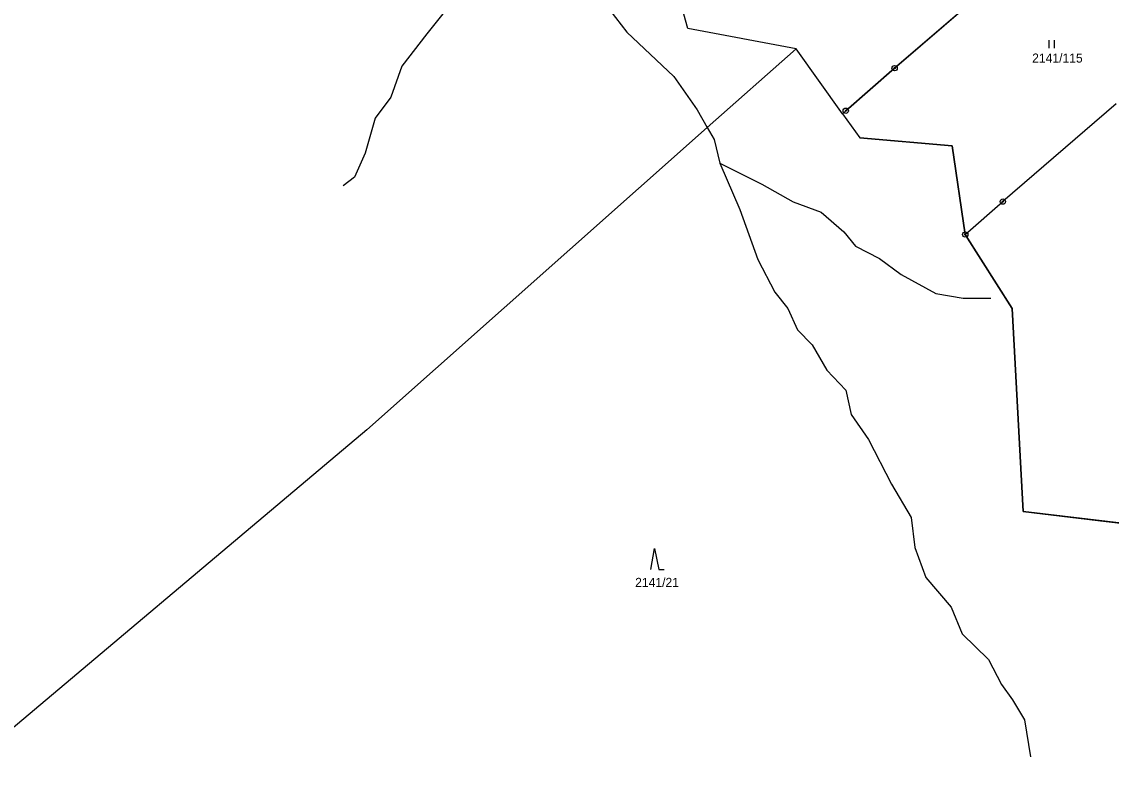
# Model space of a CAD drawing. Extents: x -439246 to -433691, y -1130252 to -1121148.
# Drawn here: x -435202 to -434997.5, y -1125793.1 to -1125650.6 of the extents above; entities that cross this region are included whole.
import ezdxf

# ---------------------------------------------------------------- set-up
doc = ezdxf.new("R2010")
doc.units = 0
for name, color, linetype in [('Vrstva 1', 7, 'Continuous'), ('Vrstva 16', 7, 'Continuous'), ('Vrstva 18', 7, 'Continuous'), ('Vrstva 24', 7, 'Continuous'), ('Vrstva 25', 7, 'Continuous'), ('Vrstva 4', 7, 'Continuous'), ('Vrstva 52', 7, 'Continuous')]:
    doc.layers.add(name, color=color, linetype=linetype)

msp = doc.modelspace()

# ---------------------------------------------------------------- linework, layer by layer
at = {"layer": 'Vrstva 1'}
for points in [[(-435038.13, -1125659.3), (-435014.64, -1125639.05)], [(-435076.96, -1125651.87), (-435078.02, -1125648.06)], [(-435056.6, -1125655.67), (-435076.96, -1125651.87)], [(-435056.6, -1125655.67), (-435073.31, -1125670.43)], [(-435047.94, -1125667.84), (-435056.6, -1125655.67)], [(-435047.31, -1125667.29), (-435038.13, -1125659.3)], [(-434996.55, -1125665.97), (-435017.82, -1125684.35)], [(-435047.31, -1125667.29), (-435047.94, -1125667.84)], [(-435047.94, -1125667.84), (-435044.69, -1125672.4)], [(-435073.31, -1125670.43), (-435137.19, -1125727.15)], [(-435027.36, -1125673.85), (-435044.69, -1125672.4)], [(-435024.88, -1125690.52), (-435027.36, -1125673.85)], [(-435024.88, -1125690.52), (-435017.82, -1125684.35)], [(-435016.08, -1125704.39), (-435024.88, -1125690.52)], [(-435013.98, -1125742.52), (-435016.08, -1125704.39)], [(-435137.19, -1125727.15), (-435215.58, -1125793.11)], [(-434962.79, -1125748.54), (-435013.98, -1125742.52)]]:
    msp.add_lwpolyline(points, dxfattribs=at)
at = {"layer": 'Vrstva 24'}
for centre, radius in [((-435038.13, -1125659.3), 0.5), ((-435038.13, -1125659.3), 0.1), ((-435047.31, -1125667.29), 0.5), ((-435047.31, -1125667.29), 0.1), ((-435017.82, -1125684.35), 0.5), ((-435017.82, -1125684.35), 0.1), ((-435024.88, -1125690.52), 0.5), ((-435024.88, -1125690.52), 0.1)]:
    msp.add_circle(centre, radius, dxfattribs=at)
at = {"layer": 'Vrstva 25'}
for p, q in [((-435009.1, -1125655.55), (-435009.1, -1125654.05)), ((-435008.1, -1125655.55), (-435008.1, -1125654.05))]:
    msp.add_line(p, q, dxfattribs=at)
msp.add_lwpolyline([(-435083.91, -1125753.41), (-435083.21, -1125749.41), (-435082.41, -1125753.41), (-435081.41, -1125753.41)], dxfattribs=at)
at = {"layer": 'Vrstva 4'}
for points in [[(-435121.18, -1125646.9), (-435125.92, -1125652.84)], [(-435091.59, -1125648.42), (-435088.4, -1125652.52)], [(-435088.4, -1125652.52), (-435079.57, -1125660.87)], [(-435125.92, -1125652.84), (-435130.62, -1125658.9)], [(-435130.62, -1125658.9), (-435132.71, -1125664.74)], [(-435079.57, -1125660.87), (-435075.17, -1125667.14)], [(-435132.71, -1125664.74), (-435135.63, -1125668.7)], [(-435135.63, -1125668.7), (-435137.5, -1125675.28)], [(-435075.17, -1125667.14), (-435073.31, -1125670.43)], [(-435073.31, -1125670.43), (-435072.03, -1125672.7)], [(-435072.03, -1125672.7), (-435070.92, -1125677.14)], [(-435137.5, -1125675.28), (-435139.55, -1125679.73)], [(-435070.92, -1125677.14), (-435067.21, -1125685.85)], [(-435070.92, -1125677.14), (-435063.09, -1125681.04)], [(-435139.55, -1125679.73), (-435141.68, -1125681.38)], [(-435063.09, -1125681.04), (-435057.21, -1125684.37)], [(-435057.21, -1125684.37), (-435051.91, -1125686.31)], [(-435067.21, -1125685.85), (-435063.79, -1125695.22)], [(-435051.91, -1125686.31), (-435047.67, -1125690.01)], [(-435047.67, -1125690.01), (-435045.45, -1125692.68)], [(-435045.45, -1125692.68), (-435040.97, -1125695.03)], [(-435063.79, -1125695.22), (-435060.63, -1125701.32)], [(-435040.97, -1125695.03), (-435036.9, -1125697.99)], [(-435036.9, -1125697.99), (-435030.38, -1125701.56)], [(-435060.63, -1125701.32), (-435058.17, -1125704.42)], [(-435030.38, -1125701.56), (-435025.29, -1125702.45)], [(-435025.29, -1125702.45), (-435020.05, -1125702.45)], [(-435058.17, -1125704.42), (-435056.35, -1125708.38)], [(-435056.35, -1125708.38), (-435053.63, -1125711.22)], [(-435053.63, -1125711.22), (-435050.85, -1125715.99)], [(-435050.85, -1125715.99), (-435047.28, -1125719.74)], [(-435047.28, -1125719.74), (-435046.28, -1125724.27)], [(-435046.28, -1125724.27), (-435043.03, -1125728.98)], [(-435043.03, -1125728.98), (-435038.7, -1125737.35)], [(-435038.7, -1125737.35), (-435035.04, -1125743.63)], [(-435035.04, -1125743.63), (-435034.34, -1125749.24)], [(-435034.34, -1125749.24), (-435032.26, -1125754.89)], [(-435032.26, -1125754.89), (-435027.52, -1125760.42)], [(-435027.52, -1125760.42), (-435025.43, -1125765.46)], [(-435025.43, -1125765.46), (-435020.54, -1125770.25)], [(-435020.54, -1125770.25), (-435018.07, -1125774.94)], [(-435018.07, -1125774.94), (-435016, -1125777.82)], [(-435016, -1125777.82), (-435013.75, -1125781.58)], [(-435013.75, -1125781.58), (-435012.61, -1125788.52)]]:
    msp.add_lwpolyline(points, dxfattribs=at)
at = {"layer": 'Vrstva 52'}
msp.add_lwpolyline([(-435021.93, -1125645.34), (-435038.13, -1125659.3), (-435047.31, -1125667.29), (-435047.94, -1125667.84), (-435044.69, -1125672.4), (-435027.36, -1125673.85), (-435024.88, -1125690.52), (-435016.08, -1125704.39), (-435013.98, -1125742.52), (-435000, -1125744.16), (-434962.79, -1125748.54)], dxfattribs=at)

# ---------------------------------------------------------------- texts
at = {"layer": 'Vrstva 16'}
msp.add_text('2141/21', height=1.7, dxfattribs=at).set_placement((-435086.84, -1125756.65))
at = {"layer": 'Vrstva 18'}
msp.add_text('2141/115', height=1.7, dxfattribs=at).set_placement((-435012.31, -1125658.25))

doc.saveas('drawing.dxf')
